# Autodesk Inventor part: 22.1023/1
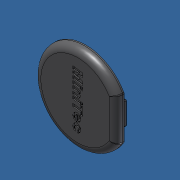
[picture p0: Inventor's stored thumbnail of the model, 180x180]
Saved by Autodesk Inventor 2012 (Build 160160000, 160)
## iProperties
Created: 2007-11
Part Number: 22.1023/1
Material: ABS Plastic
Document SubType Name: Modeling
Designer: Andy Moles
Mass: 2.08108 g
Surface Area: 22.4529 cm^2
Volume: 1.96328 cm^3
Density: 1.06 g/cm^3
Description: END CAP FOR HANDLE PROFILE 32
Vendor: S
Author: Andy Moles
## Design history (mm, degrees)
feature "Base1"
body "Solid1"
